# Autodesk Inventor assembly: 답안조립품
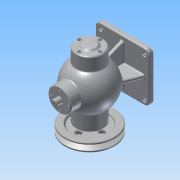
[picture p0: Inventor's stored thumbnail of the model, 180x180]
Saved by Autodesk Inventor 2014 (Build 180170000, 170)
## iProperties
Created: 2017-01
Part Number: 답안조립품
Document SubType Name: Assembly
Designer: ksu
Author: ksu
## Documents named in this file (19)
- C:\Users\ksu\Desktop\470118V1005\470118V1005\답안조립품.iam
- C:\Users\ksu\Desktop\470118V1005\470118V1005\1본체.ipt
- C:\Users\ksu\Desktop\470118V1005\470118V1005\V-벨트풀리.ipt
- C:\Users\ksu\Desktop\470118V1005\470118V1005\너트 M8.ipt
- C:\Users\ksu\Desktop\470118V1005\470118V1005\뒤커버.ipt
- C:\Users\ksu\Desktop\470118V1005\470118V1005\멈춤링- 15 x 1.ipt
- C:\Users\ksu\Desktop\470118V1005\470118V1005\멈춤링- 35x1.6.ipt
- KS B 1336 - 35x1.6.ipt
- C:\Users\ksu\Desktop\470118V1005\470118V1005\베어링- 6202.ipt
- KS B 2023 - 6202 - 15 x 35 x 11 - 7.8.ipt
- C:\Users\ksu\Desktop\470118V1005\470118V1005\볼트 M4 x 12.ipt
- C:\Users\ksu\Desktop\470118V1005\470118V1005\볼트 M4 x 16.ipt
- C:\Users\ksu\Desktop\470118V1005\470118V1005\부시.ipt
- C:\Users\ksu\Desktop\470118V1005\470118V1005\상부커버.ipt
- C:\Users\ksu\Desktop\470118V1005\470118V1005\슬라이드.ipt
- C:\Users\ksu\Desktop\470118V1005\470118V1005\앞커버.ipt
- C:\Users\ksu\Desktop\470118V1005\470118V1005\오일실 15 30 7.ipt
- C:\Users\ksu\Desktop\470118V1005\470118V1005\키 4 x 4 x 12.ipt
- C:\Users\ksu\Desktop\470118V1005\470118V1005\편심축.ipt
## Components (17 placed, 6 different names)
1. 1본체:1 — Insert:11, Insert:12, Insert:13, Mate:3, Mate:4, Mate:5, Mate:6, Mate:7, Mate:8, Mate:9, Mate:12, Mate:13, Insert:25
2. V-벨트풀리:1 — Insert:3, Mate:1, Insert:14
3. KS B 1336 - 35x1.6:1 — Insert:25, Mate:15
4. KS B 2023 - 6202 - 15 x 35 x 11 - 7.8:1 — Insert:6, Insert:7
5. KS B 1021 - 에 따름 ISO 1207 - 미터 A  M 4 x 12:1 — Mate:9, Mate:13
6. ISO 4762 M4 x 16:1 — Insert:20
7. KS B 2023 - 6202 - 15 x 35 x 11 - 7.8:2 — Mate:14, Mate:15
8. ISO 4762 M4 x 16:2 — Insert:15
9. ISO 4762 M4 x 16:3 — Insert:22
10. ISO 4762 M4 x 16:4 — Insert:16
11. ISO 4762 M4 x 16:5 — Insert:17
12. ISO 4762 M4 x 16:6 — Insert:18
13. ISO 4762 M4 x 16:7 — Insert:19
14. ISO 4762 M4 x 16:8 — Insert:21
15. KS B 1021 - 에 따름 ISO 1207 - 미터 A  M 4 x 12:2 — Mate:8, Mate:12
16. KS B 1021 - 에 따름 ISO 1207 - 미터 A  M 4 x 12:3 — Mate:7, Mate:10
17. KS B 1021 - 에 따름 ISO 1207 - 미터 A  M 4 x 12:4 — Mate:6, Mate:11
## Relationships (30: Insert 16, Mate 14)
- Insert:3: V-벨트풀리:1
- Mate:1: V-벨트풀리:1
- Insert:6: KS B 2023 - 6202 - 15 x 35 x 11 - 7.8:1
- Insert:7: KS B 2023 - 6202 - 15 x 35 x 11 - 7.8:1
- Insert:11: 1본체:1
- Insert:12: 1본체:1
- Insert:13: 1본체:1
- Insert:14: V-벨트풀리:1
- Mate:3: 1본체:1
- Mate:4: 1본체:1
- Insert:15: ISO 4762 M4 x 16:2
- Insert:16: ISO 4762 M4 x 16:4
- Insert:17: ISO 4762 M4 x 16:5
- Insert:18: ISO 4762 M4 x 16:6
- Insert:19: ISO 4762 M4 x 16:7
- Insert:20: ISO 4762 M4 x 16:1
- Insert:21: ISO 4762 M4 x 16:8
- Insert:22: ISO 4762 M4 x 16:3
- Mate:5: 1본체:1
- Mate:6: 1본체:1 ↔ KS B 1021 - 에 따름 ISO 1207 - 미터 A  M 4 x 12:4
- Mate:7: 1본체:1 ↔ KS B 1021 - 에 따름 ISO 1207 - 미터 A  M 4 x 12:3
- Mate:8: 1본체:1 ↔ KS B 1021 - 에 따름 ISO 1207 - 미터 A  M 4 x 12:2
- Mate:9: 1본체:1 ↔ KS B 1021 - 에 따름 ISO 1207 - 미터 A  M 4 x 12:1
- Mate:10: KS B 1021 - 에 따름 ISO 1207 - 미터 A  M 4 x 12:3
- Mate:11: KS B 1021 - 에 따름 ISO 1207 - 미터 A  M 4 x 12:4
- Mate:12: 1본체:1 ↔ KS B 1021 - 에 따름 ISO 1207 - 미터 A  M 4 x 12:2
- Mate:13: 1본체:1 ↔ KS B 1021 - 에 따름 ISO 1207 - 미터 A  M 4 x 12:1
- Insert:25: 1본체:1 ↔ KS B 1336 - 35x1.6:1
- Mate:14: KS B 2023 - 6202 - 15 x 35 x 11 - 7.8:2
- Mate:15: KS B 1336 - 35x1.6:1 ↔ KS B 2023 - 6202 - 15 x 35 x 11 - 7.8:2
